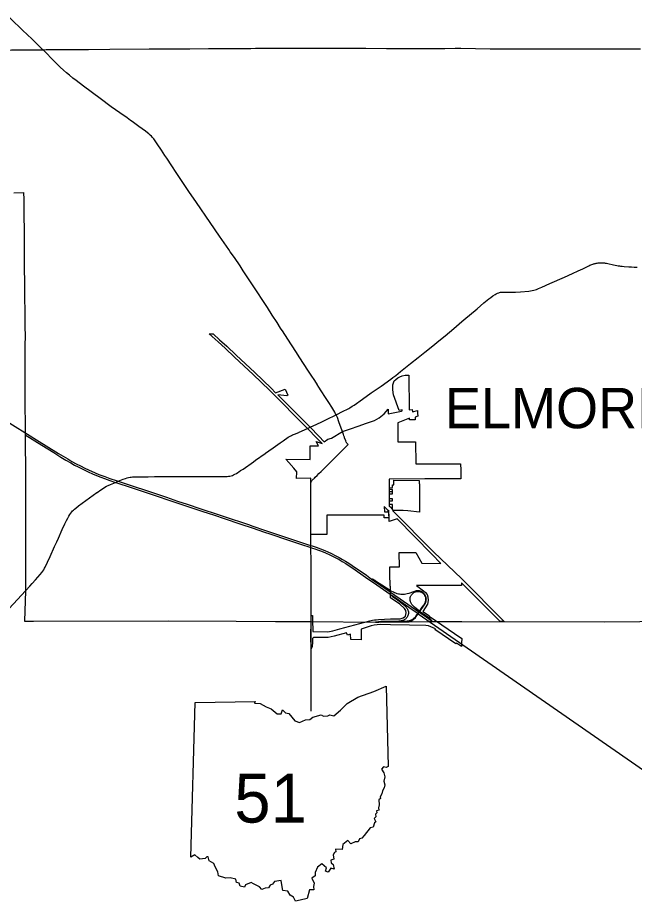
# Model space of a CAD drawing. Extents: x -82 to 873, y 0 to 440.
# Drawn here: x 144.2 to 201.4, y 99.3 to 181.3 of the extents above; entities that cross this region are included whole.
import ezdxf

# ---------------------------------------------------------------- set-up
doc = ezdxf.new("R2010")
doc.units = 0
for name, color, linetype in [('DV_X_Corp_Line', 7, 'Continuous'), ('GM_X_Corporation_Text', 7, 'Continuous'), ('GM_X_County', 7, 'Continuous'), ('GM_X_Interchange_Ramps', 7, 'Continuous'), ('GM_X_Interstate_Route', 7, 'Continuous'), ('PV_P_Text', 7, 'Continuous')]:
    doc.layers.add(name, color=color, linetype=linetype)

msp = doc.modelspace()

# ---------------------------------------------------------------- linework, layer by layer
at = {"layer": 'DV_X_Corp_Line'}
for points in [[(179.016, 136.129), (178.715, 136.13), (178.711, 136.47), (179.014, 136.47), (179.014, 136.675), (178.714, 136.673), (178.714, 137.127), (179.014, 137.127), (179.014, 137.3), (178.716, 137.303), (178.716, 137.341), (179.013, 137.336), (179.008, 137.524), (178.715, 137.518), (178.717, 137.692), (179.014, 137.701), (179.014, 137.971), (179.121, 137.969), (179.121, 138.394), (181.477, 138.368), (181.484, 138.061), (181.499, 138.061), (181.5, 135.421), (180.425, 135.553), (180, 135.568), (179, 135.585), (182.828, 131.714), (185.396, 129.272), (189.374, 125.272), (189.003, 125.269), (185.4, 128.867), (185.402, 128.61), (181.24, 128.609), (181.868, 128.129), (182.061, 127.98), (182.212, 127.777), (182.287, 127.55), (182.313, 127.229), (182.239, 126.882), (181.822, 126.214), (182.425, 125.789), (182.418, 125.779), (184.746, 124.15), (185.423, 123.712), (185.418, 123.308), (185.418, 122.954), (184.928, 123.275), (184.893, 123.195), (182.927, 124.523), (182.979, 124.593), (182.34, 124.875), (182.091, 124.912), (180.589, 124.944), (178.818, 124.972), (177.857, 124.998), (177.579, 124.975), (177.295, 124.931), (177.037, 124.866), (176.088, 124.577), (176.1, 123.575), (175.13, 123.592), (175.119, 124.111), (174.835, 124.015), (174.729, 124.217), (173.589, 123.905), (173.027, 123.794), (171.669, 123.789), (171.588, 123.69), (171.584, 123.581), (171.582, 123.347), (171.558, 122.96), (171.439, 122.724), (171.436, 123.903), (171.457, 125.272), (171.454, 125.599), (171.454, 125.836), (171.569, 125.836), (171.575, 125.423), (171.617, 124.334), (172.997, 124.31), (173.463, 124.397), (174.112, 124.595), (176.891, 125.324), (177.139, 125.389), (177.33, 125.432), (177.494, 125.445), (177.712, 125.463), (178.813, 125.508), (179.704, 125.518), (180.003, 125.606), (180.195, 125.758), (180.281, 126.064), (180.226, 126.288), (180.108, 126.472), (179.68, 126.888), (178.829, 127.485), (178.826, 127.79), (178.825, 128), (178.815, 128.567), (178.775, 128.566), (178.774, 128.893), (178.768, 129.372), (178.766, 129.756), (178.76, 130.34), (179.652, 130.335), (179.612, 131.672), (181.159, 131.675), (181.739, 130.694), (183.503, 130.668), (182.651, 131.538), (179.433, 134.791), (178.681, 134.57), (178.666, 135.576), (178.632, 135.6), (178.65, 134.888), (178.214, 134.889), (178.219, 135.16), (172.91, 135.139), (172.92, 133.338), (171.428, 133.348), (171.427, 133.873), (171.425, 134.467), (171.424, 134.929), (171.423, 135.591), (171.422, 135.727), (171.423, 136.756), (171.423, 137.167), (171.414, 137.659), (171.411, 137.825), (171.413, 137.985), (171.416, 138.046), (171.414, 138.574), (170.079, 138.564), (170.11, 139.154), (169.837, 139.512), (169.37, 140.04), (169.101, 140.347), (171.357, 140.315), (171.374, 141.578), (172.134, 141.569), (171.922, 141.971), (172.47, 141.797), (171.983, 142.306), (171.124, 143.192), (167.572, 146.745), (166.084, 148.195), (164.34, 149.801), (163.464, 150.646), (162.813, 151.236), (161.979, 151.978), (162.296, 151.984), (162.365, 151.986), (162.956, 151.416), (163.62, 150.822), (164.501, 149.984), (166.234, 148.388), (167.743, 146.92), (168.155, 146.508), (169.039, 146.847), (169.279, 146.295), (169.195, 146.219), (168.353, 146.31), (171.365, 143.3), (172.172, 142.467), (172.648, 141.96), (172.998, 142.196), (173.339, 142.304), (174.353, 142.897), (174.719, 143.046), (175.094, 143.17), (175.808, 143.405), (176.603, 143.688), (177.335, 143.927), (177.761, 144.175), (178.232, 144.563), (178.596, 144.992), (178.589, 144.537), (179.847, 144.81), (179.915, 144.825), (179.886, 144.932), (179.634, 144.865), (179.109, 146.318), (179.047, 146.769), (179.024, 147.245), (179.087, 147.428), (179.169, 147.615), (179.297, 147.749), (179.491, 147.893), (179.681, 147.999), (179.892, 148.077), (180.187, 148.149), (180.504, 148.155), (180.558, 144.922), (180.83, 144.964), (180.846, 144.734), (181.315, 144.846), (181.319, 144.797), (181.332, 144.62), (181.349, 144.324), (181.111, 144.247), (181.113, 144.006), (180.59, 143.987), (180.585, 144.142), (179.497, 143.712), (179.507, 141.967), (181.141, 141.961), (181.16, 139.899), (185.328, 139.899), (185.335, 139.333), (185.338, 139.02), (185.336, 138.723), (185.33, 138.513), (185.232, 138.515), (184.46, 138.513), (183.965, 138.511), (183.93, 138.511), (183.515, 138.51), (182.824, 138.511), (182.528, 138.51), (182.208, 138.508), (181.999, 138.506), (178.682, 138.484), (178.681, 138.206), (178.683, 137.845), (178.685, 137.707), (178.687, 137.534), (178.688, 137.4), (178.689, 137.358), (178.69, 137.142), (178.691, 136.917), (178.692, 136.69), (178.692, 136.542), (178.693, 136.338), (178.692, 135.979), (178.737, 135.935), (178.778, 135.904), (179.004, 135.682)], [(178.255, 135.463), (178.614, 135.469), (178.611, 135.593), (178.241, 135.959)]]:
    msp.add_lwpolyline(points, close=True, dxfattribs=at)
at = {"layer": 'GM_X_County'}
msp.add_lwpolyline([(143.85, 165.07), (144.77, 165.089), (144.77, 165.041), (144.78, 164.504), (144.789, 163.971), (144.79, 163.519), (144.796, 163.15), (144.798, 162.74), (144.811, 161.795), (144.814, 161.344), (144.824, 160.604), (144.827, 159.823), (144.829, 159.251), (144.833, 157.978), (144.845, 156.829), (144.861, 155.064), (144.866, 154.325), (144.878, 153.422), (144.894, 152.599), (144.896, 151.825), (144.883, 150.878), (144.878, 149.313), (144.881, 148.294), (144.89, 145.706), (144.895, 144.846), (144.896, 144.066), (144.904, 143.224), (144.905, 143.012), (144.907, 142.801), (144.907, 142.592), (144.912, 142.094), (144.913, 141.559), (144.916, 141.23), (144.929, 139.958), (144.931, 139.674), (144.935, 139.26), (144.939, 138.645), (144.941, 138.357), (144.937, 137.742), (144.937, 137.249), (144.935, 136.51), (144.936, 135.032), (144.94, 133.883), (144.942, 132.323), (144.95, 129.655), (144.947, 128.546), (144.95, 128.402), (144.955, 128.137), (144.843, 125.317), (145.683, 125.315), (158.213, 125.324), (164.501, 125.302), (168.138, 125.28), (171.457, 125.272), (177.433, 125.221), (177.739, 125.221), (178.815, 125.23), (180.54, 125.248), (182.454, 125.267), (182.74, 125.268), (185.433, 125.276), (198.647, 125.256), (205.258, 125.298)], dxfattribs=at)
at = {"layer": 'GM_X_Interchange_Ramps'}
for points in [[(180.54, 125.248), (180.607, 125.267), (180.666, 125.285), (180.727, 125.307), (180.804, 125.345), (180.87, 125.387), (180.931, 125.426), (180.994, 125.482), (181.056, 125.541), (181.126, 125.629), (181.202, 125.726), (181.397, 126.001), (181.493, 126.137), (181.541, 126.205), (181.882, 126.699), (181.995, 126.869), (182.056, 126.976), (182.089, 127.051), (182.103, 127.089), (182.125, 127.168), (182.139, 127.248), (182.144, 127.33), (182.14, 127.411), (182.128, 127.492), (182.108, 127.572), (182.079, 127.648), (182.043, 127.722), (182, 127.791), (181.949, 127.856), (181.892, 127.914), (181.83, 127.967), (181.763, 128.014), (181.691, 128.053), (181.615, 128.084), (181.576, 128.097), (181.496, 128.116), (181.456, 128.122), (181.375, 128.127), (181.334, 128.127), (181.252, 128.12), (181.212, 128.114), (181.093, 128.084), (180.937, 128.033), (180.512, 127.884), (180.355, 127.836), (180.236, 127.808), (180.114, 127.79), (180.033, 127.783), (179.91, 127.781), (179.788, 127.788), (179.666, 127.802), (179.545, 127.824), (179.425, 127.853), (179.308, 127.89), (179.194, 127.934), (179.082, 127.985), (178.937, 128.06), (178.825, 128.126), (178.784, 128.151), (178.449, 128.362), (178.252, 128.49), (177.524, 128.967), (177.367, 129.072), (177.292, 129.118), (177.218, 129.161), (177.197, 129.172), (177.179, 129.181), (177.141, 129.195), (177.125, 129.202), (177.099, 129.21), (177.062, 129.219)], [(182.669, 125.316), (182.624, 125.381), (182.606, 125.406), (182.579, 125.437), (182.552, 125.468), (182.498, 125.52), (182.401, 125.601), (182.367, 125.624), (181.983, 125.887), (181.613, 126.151), (181.541, 126.205), (181.385, 126.326), (181.196, 126.482), (181.042, 126.618), (180.951, 126.701), (180.865, 126.789), (180.812, 126.851), (180.763, 126.917), (180.721, 126.988), (180.702, 127.024), (180.671, 127.1), (180.658, 127.138), (180.639, 127.218), (180.631, 127.299), (180.631, 127.381), (180.641, 127.462), (180.649, 127.503), (180.672, 127.581), (180.703, 127.657), (180.722, 127.694), (180.765, 127.764), (180.817, 127.827), (180.845, 127.857), (180.907, 127.91), (180.94, 127.934), (180.975, 127.956), (181.048, 127.993), (181.124, 128.023), (181.204, 128.045), (181.284, 128.058), (181.366, 128.063), (181.448, 128.058), (181.489, 128.052), (181.569, 128.034), (181.608, 128.021), (181.683, 127.989), (181.719, 127.97), (181.788, 127.925), (181.82, 127.9), (181.88, 127.844), (181.933, 127.782), (181.979, 127.714), (182.017, 127.641), (182.034, 127.603), (182.059, 127.525), (182.068, 127.486), (182.08, 127.405), (182.082, 127.364), (182.079, 127.282), (182.068, 127.201), (182.048, 127.122), (182.035, 127.083), (182.004, 127.008), (181.967, 126.935), (181.903, 126.829), (181.739, 126.594), (181.443, 126.173), (181.346, 126.038), (181.337, 126.025), (181.171, 125.79), (181.097, 125.692), (181.044, 125.63), (180.987, 125.571), (180.926, 125.516), (180.862, 125.466), (180.793, 125.422), (180.72, 125.385), (180.644, 125.354), (180.564, 125.329), (180.486, 125.312), (180.365, 125.295), (180.241, 125.289), (179.97, 125.288), (179.581, 125.294), (178.817, 125.277), (178.715, 125.277), (177.921, 125.272), (177.699, 125.257), (177.433, 125.221)], [(178.826, 127.79), (178.894, 127.712), (178.951, 127.651), (179.017, 127.599), (179.09, 127.545), (179.48, 127.273), (179.677, 127.126), (179.869, 126.973), (180.055, 126.812), (180.175, 126.7), (180.26, 126.612), (180.312, 126.549), (180.359, 126.482), (180.4, 126.411), (180.434, 126.336), (180.461, 126.259), (180.478, 126.179), (180.486, 126.098), (180.486, 126.057), (180.483, 126.016), (180.471, 125.936), (180.461, 125.896), (180.435, 125.818), (180.401, 125.743), (180.36, 125.672), (180.312, 125.606), (180.256, 125.546), (180.226, 125.518), (180.194, 125.493), (180.126, 125.447), (180.065, 125.411), (179.978, 125.371), (179.934, 125.355), (179.883, 125.34), (179.847, 125.332), (179.818, 125.325), (179.747, 125.313), (179.695, 125.305), (179.581, 125.294)]]:
    msp.add_lwpolyline(points, dxfattribs=at)
at = {"layer": 'GM_X_Interstate_Route'}
msp.add_line((109.105, 164.804), (145.117, 142.669), dxfattribs=at)
for points in [[(146.548, 178.353), (146.523, 178.377), (146.166, 178.724), (145.614, 179.254), (145.028, 179.812), (144.75, 180.079), (144.343, 180.47), (143.892, 180.895), (143.546, 181.233), (143.505, 181.272), (143.449, 181.324)], [(141.437, 178.319), (143.641, 178.332), (144.298, 178.338), (144.728, 178.343), (145.621, 178.347), (146.548, 178.353)], [(146.548, 178.353), (146.852, 178.355), (148.165, 178.362), (149.027, 178.371), (150.791, 178.379), (152.761, 178.394), (156.413, 178.419), (157.726, 178.432), (158.017, 178.434), (160.189, 178.446), (161.912, 178.454), (162.856, 178.46), (163.964, 178.464), (164.422, 178.467)], [(171.58, 147.954), (171.335, 148.329), (171.152, 148.62), (170.413, 149.756), (170.032, 150.341), (169.294, 151.477), (169.066, 151.818), (168.939, 152.019), (168.847, 152.164), (168.623, 152.509), (168.291, 153.027), (167.845, 153.716), (167.399, 154.406), (167.156, 154.786), (166.91, 155.165), (166.511, 155.787), (165.833, 156.815), (165.149, 157.839), (164.856, 158.285), (164.325, 159.066), (163.948, 159.604), (163.814, 159.798), (163.389, 160.415), (162.943, 161.055), (162.081, 162.305), (160.809, 164.17), (160.115, 165.197), (158.932, 166.964), (158.523, 167.579), (158.059, 168.278), (157.886, 168.536), (157.564, 169.012), (157.154, 169.627), (156.968, 169.898), (156.846, 170.064), (156.743, 170.192), (156.632, 170.314), (156.515, 170.43), (156.392, 170.54), (156.265, 170.644), (156.068, 170.793), (155.469, 171.226), (154.832, 171.676), (154.689, 171.779), (154.366, 172.013), (153.696, 172.486), (152.897, 173.063), (151.87, 173.814), (150.323, 174.967), (149.634, 175.485), (149.344, 175.713), (149.026, 175.973), (148.746, 176.213), (148.471, 176.459), (148.171, 176.739), (147.614, 177.284), (146.647, 178.262), (146.548, 178.353)], [(164.422, 178.467), (165.277, 178.473), (165.852, 178.474), (166.303, 178.48), (168.396, 178.488), (168.888, 178.495), (169.956, 178.496), (171.314, 178.496), (171.556, 178.496), (172.048, 178.498), (172.91, 178.491), (173.533, 178.492), (173.895, 178.493), (175.742, 178.49), (176.398, 178.484), (176.519, 178.484), (178.45, 178.477), (179.763, 178.468), (181.035, 178.461), (181.651, 178.458), (182.677, 178.462), (183.867, 178.473), (184.81, 178.486), (185.237, 178.488), (185.344, 178.488), (188.052, 178.446), (190.063, 178.433), (190.966, 178.43), (191.664, 178.431), (192.443, 178.429), (193.141, 178.429), (194.823, 178.429), (196.465, 178.432), (197.286, 178.432), (198.353, 178.436), (198.445, 178.436), (198.968, 178.437), (199.625, 178.441), (200.446, 178.437), (202.005, 178.428)], [(173.774, 144.472), (174.421, 144.785), (174.836, 144.991), (174.946, 145.05), (175.049, 145.111), (175.268, 145.248), (175.45, 145.371), (176.231, 145.921), (177.036, 146.493), (177.942, 147.129), (178.835, 147.764), (179.046, 147.914), (179.308, 148.111), (179.759, 148.466), (180.683, 149.216), (181.386, 149.782), (181.993, 150.272), (182.731, 150.861), (183.306, 151.324), (183.878, 151.791), (184.291, 152.128), (184.7, 152.471), (185.44, 153.107), (185.634, 153.273), (186.854, 154.309), (187.167, 154.574), (187.479, 154.84), (187.794, 155.103), (187.955, 155.23), (188.121, 155.352), (188.324, 155.491), (188.532, 155.624), (188.639, 155.686), (188.75, 155.741), (188.865, 155.788), (188.944, 155.814), (189.024, 155.834), (189.106, 155.848), (189.188, 155.856), (189.312, 155.86), (189.64, 155.853), (189.845, 155.847), (190.132, 155.85), (190.419, 155.86), (190.868, 155.891), (191.646, 155.952), (191.808, 155.971), (191.969, 155.998), (192.129, 156.034), (192.247, 156.067), (192.363, 156.106), (192.553, 156.18), (192.854, 156.312), (193.603, 156.646), (194.957, 157.242), (195.703, 157.574), (196.228, 157.811), (196.67, 158.023), (197.222, 158.293), (197.308, 158.338), (197.408, 158.382), (197.502, 158.42), (197.582, 158.449), (197.658, 158.473), (197.719, 158.49), (197.786, 158.507), (197.849, 158.52), (197.913, 158.531), (197.993, 158.544), (198.075, 158.553), (198.165, 158.561), (198.291, 158.568), (198.414, 158.57), (198.536, 158.566), (198.567, 158.564), (198.664, 158.557), (198.742, 158.548), (198.803, 158.539), (198.86, 158.528), (198.988, 158.5), (199.507, 158.381), (199.676, 158.343), (199.826, 158.313), (199.933, 158.293), (200.055, 158.274), (200.167, 158.261), (200.328, 158.245), (200.508, 158.232), (200.926, 158.2), (201.173, 158.186), (201.438, 158.169), (201.723, 158.156)], [(173.774, 144.472), (173.724, 144.565), (173.646, 144.709), (173.559, 144.849), (173.363, 145.162), (173.08, 145.615), (172.794, 146.065), (172.391, 146.685), (172.171, 147.031), (172.015, 147.273), (171.998, 147.3), (171.663, 147.827), (171.58, 147.954)], [(171.37, 143.303), (171.994, 143.588), (172.442, 143.797), (172.808, 143.983), (173.139, 144.151), (173.193, 144.177), (173.472, 144.313), (173.774, 144.472)], [(174.447, 142.634), (174.353, 142.897), (174.288, 143.079), (174.06, 143.718), (174.023, 143.82), (173.884, 144.206), (173.837, 144.322), (173.81, 144.387), (173.774, 144.472)], [(144.907, 142.801), (145.117, 142.669), (145.96, 142.147), (148.018, 140.872), (148.86, 140.361), (149.25, 140.135), (149.646, 139.918), (150.046, 139.709), (150.45, 139.508), (150.784, 139.351), (151.421, 139.069), (151.763, 138.929), (152.299, 138.724), (152.762, 138.556), (153.344, 138.359), (153.547, 138.292), (154.277, 138.05), (156.809, 137.212), (158.015, 136.808), (159.064, 136.452), (159.96, 136.157), (161.206, 135.744), (162.725, 135.241), (163.385, 135.016), (165.644, 134.265), (166.052, 134.126), (167.127, 133.76), (171.205, 132.399), (171.427, 132.325), (171.557, 132.287), (171.906, 132.166), (172.329, 132.01), (172.71, 131.858), (173.012, 131.728), (173.347, 131.573), (173.679, 131.411), (174.043, 131.221), (174.365, 131.041), (174.648, 130.874), (174.96, 130.678), (175.268, 130.474), (176.583, 129.562), (177.062, 129.219), (177.875, 128.66), (178.781, 128.031), (178.825, 128), (179.704, 127.389), (181.443, 126.173), (181.493, 126.137), (182.115, 125.704), (182.669, 125.316), (182.74, 125.268)], [(155.311, 138.705), (155.42, 138.708), (156.32, 138.713), (156.901, 138.72), (157.757, 138.725), (158.162, 138.726), (158.455, 138.727), (158.868, 138.728), (159.235, 138.73), (160.427, 138.732), (161.781, 138.738), (162.232, 138.738), (162.972, 138.742), (163.489, 138.744), (163.667, 138.749), (163.792, 138.758), (163.913, 138.777), (164.031, 138.804), (164.147, 138.842), (164.26, 138.89), (164.37, 138.944), (164.512, 139.024), (164.86, 139.245), (164.909, 139.277), (165.135, 139.423), (166.112, 140.107), (166.302, 140.244), (167.178, 140.871), (167.214, 140.897), (167.512, 141.107), (167.917, 141.396), (168.583, 141.868), (168.854, 142.054), (169.333, 142.372), (169.508, 142.48), (169.616, 142.541), (169.726, 142.595), (169.915, 142.677), (170.297, 142.828), (170.343, 142.848)], [(170.343, 142.848), (171.124, 143.192), (171.129, 143.194)], [(171.129, 143.194), (171.365, 143.3), (171.37, 143.303)], [(144.907, 142.592), (146.452, 141.639), (147.569, 140.949), (148.229, 140.535), (148.686, 140.261), (149.146, 139.993), (149.504, 139.794), (149.831, 139.623), (150.271, 139.403), (150.752, 139.174), (151.163, 138.99), (151.539, 138.829), (151.919, 138.676), (152.264, 138.546), (152.767, 138.371), (153.3, 138.191), (153.335, 138.18)], [(174.492, 142.51), (174.447, 142.634)], [(174.891, 141.703), (174.863, 141.722), (174.838, 141.74), (174.811, 141.766), (174.784, 141.798), (174.76, 141.834), (174.734, 141.877), (174.708, 141.933), (174.664, 142.04), (174.563, 142.315), (174.542, 142.373), (174.492, 142.51)], [(174.032, 140.845), (174.367, 141.178), (174.891, 141.703)], [(171.421, 138.093), (171.421, 138.097), (171.432, 138.151), (171.446, 138.199), (171.465, 138.244), (171.494, 138.304), (171.523, 138.343), (171.562, 138.39), (171.617, 138.45), (171.645, 138.477), (171.692, 138.524), (171.754, 138.587), (171.831, 138.661), (172.008, 138.837), (172.18, 139.004), (172.382, 139.209), (172.585, 139.412), (172.626, 139.451), (172.826, 139.642), (172.992, 139.809), (173.52, 140.336), (173.64, 140.454), (174.032, 140.845)], [(151.559, 137.237), (151.593, 137.262), (151.929, 137.499), (152.168, 137.659), (152.308, 137.746), (152.452, 137.826), (152.599, 137.899), (152.825, 137.998), (153.3, 138.191), (153.547, 138.292), (154.005, 138.479), (154.214, 138.555), (154.363, 138.601), (154.51, 138.64), (154.641, 138.665), (154.76, 138.681), (154.885, 138.691), (155.047, 138.699), (155.311, 138.705)], [(153.335, 138.18), (154.75, 137.704), (157.163, 136.901), (158.252, 136.538), (160.198, 135.889), (161.403, 135.485), (162.377, 135.163), (163.466, 134.799), (164.829, 134.347), (166.077, 133.93), (167.034, 133.61), (167.706, 133.382), (169.261, 132.861), (170.468, 132.461), (171.426, 132.142), (171.571, 132.094)], [(171.426, 133.997), (171.425, 134.467), (171.424, 134.929), (171.423, 135.591), (171.422, 135.727), (171.423, 136.756), (171.423, 137.167), (171.414, 137.659), (171.411, 137.825), (171.413, 137.985), (171.416, 138.046), (171.421, 138.093)], [(139.193, 121.929), (145.336, 128.548), (145.557, 128.791), (145.857, 129.129), (146.318, 129.653), (146.448, 129.811), (146.545, 129.942), (146.634, 130.079), (146.719, 130.22), (146.777, 130.327), (146.989, 130.772), (147.228, 131.295), (147.648, 132.231), (147.85, 132.681), (148.002, 133.017), (148.351, 133.806), (148.591, 134.328), (148.75, 134.662), (148.864, 134.881), (148.966, 135.06), (149.052, 135.2), (149.145, 135.336), (149.246, 135.467), (149.309, 135.539), (149.384, 135.617), (149.478, 135.701), (149.606, 135.805), (149.87, 136.002), (150.216, 136.255), (151.559, 137.237)], [(171.428, 133.336), (171.428, 133.348), (171.427, 133.873), (171.426, 133.997)], [(171.429, 132.014), (171.426, 132.142), (171.427, 132.325), (171.432, 132.859), (171.428, 133.336)], [(171.571, 132.094), (171.791, 132.022), (172.14, 131.898), (172.408, 131.794), (172.787, 131.635), (173.199, 131.451), (173.496, 131.31), (173.753, 131.18), (174.041, 131.022), (174.326, 130.858), (174.678, 130.645), (174.989, 130.447), (175.33, 130.218), (176.508, 129.396), (177.552, 128.671), (178.157, 128.247), (178.783, 127.819), (178.826, 127.79), (179.037, 127.644)], [(171.455, 116.945), (171.454, 125.836), (171.454, 125.927), (171.455, 125.987), (171.457, 126.378), (171.455, 127.527), (171.453, 128.06), (171.449, 128.593), (171.446, 129.537), (171.444, 130.234), (171.44, 131.136), (171.436, 131.792), (171.429, 132.014)], [(179.037, 127.644), (179.774, 127.133), (180.746, 126.456)], [(180.746, 126.456), (181.346, 126.038), (181.397, 126.001), (210.684, 105.646)], [(171.457, 125.272), (171.454, 125.599), (171.454, 125.801)]]:
    msp.add_lwpolyline(points, dxfattribs=at)
at = {"layer": 'PV_P_Text'}
msp.add_line((160.293, 103.406), (160.694, 117.769), dxfattribs=at)
msp.add_line((160.293, 103.406), (160.694, 117.769), dxfattribs=at)
for points in [[(160.694, 117.769), (166.267, 117.863), (166.18, 117.689), (166.706, 117.653), (167.264, 117.346), (167.736, 117.153), (168.314, 116.696), (168.66, 116.701), (168.806, 117.075), (169.071, 116.786), (169.385, 116.735), (169.929, 116.047), (170.377, 115.899), (170.914, 116.134), (171.316, 116.173), (171.609, 116.406), (172.374, 116.605), (172.587, 116.486), (172.992, 116.51), (173.196, 116.598), (173.549, 116.519), (174.17, 117.042), (174.81, 117.658), (175.794, 118.239), (177.264, 118.789), (178.427, 119.282), (178.595, 111.828)], [(160.694, 117.769), (166.267, 117.863), (166.18, 117.689), (166.706, 117.653), (167.264, 117.346), (167.736, 117.153), (168.314, 116.696), (168.66, 116.701), (168.806, 117.075), (169.071, 116.786), (169.385, 116.735), (169.929, 116.047), (170.377, 115.899), (170.914, 116.134), (171.316, 116.173), (171.609, 116.406), (172.374, 116.605), (172.587, 116.486), (172.992, 116.51), (173.196, 116.598), (173.549, 116.519), (174.17, 117.042), (174.81, 117.658), (175.794, 118.239), (177.264, 118.789), (178.427, 119.282), (178.595, 111.828)], [(178.595, 111.828), (178.424, 111.724), (178.157, 111.773), (177.977, 111.564), (178.199, 111.215), (178.304, 110.847), (178.211, 110.44), (178.303, 110.105), (178.241, 109.825), (178.073, 109.546), (178.015, 109.28), (177.872, 109), (177.884, 108.843), (177.748, 108.719), (177.773, 108.252), (177.704, 107.994), (177.728, 107.771), (177.507, 107.713), (177.558, 107.529), (177.417, 107.386), (177.447, 107.142), (177.288, 106.986), (177.443, 106.673), (177.319, 106.574), (177.216, 106.193), (176.933, 106.116), (176.366, 105.421), (176.166, 105.158), (175.941, 105.092), (175.818, 104.822), (175.541, 104.821), (175.123, 104.634), (174.852, 104.956), (174.378, 104.568), (174.323, 104.12), (173.724, 104.135), (173.747, 103.908), (173.613, 103.842), (173.491, 103.615), (173.562, 103.212), (173.282, 103.11), (173.316, 102.875), (173.495, 102.732), (173.575, 102.285), (173.277, 102.376), (173.033, 101.999), (172.782, 102.087), (172.864, 102.407), (172.439, 102.79), (172.037, 102.483), (171.828, 101.991), (171.826, 101.661), (171.526, 101.461), (171.718, 100.994), (171.683, 100.672), (171.689, 100.367), (171.315, 100.377), (171.089, 99.553)], [(178.595, 111.828), (178.424, 111.724), (178.157, 111.773), (177.977, 111.564), (178.199, 111.215), (178.304, 110.847), (178.211, 110.44), (178.303, 110.105), (178.241, 109.825), (178.073, 109.546), (178.015, 109.28), (177.872, 109), (177.884, 108.843), (177.748, 108.719), (177.773, 108.252), (177.704, 107.994), (177.728, 107.771), (177.507, 107.713), (177.558, 107.529), (177.417, 107.386), (177.447, 107.142), (177.288, 106.986), (177.443, 106.673), (177.319, 106.574), (177.216, 106.193), (176.933, 106.116), (176.366, 105.421), (176.166, 105.158), (175.941, 105.092), (175.818, 104.822), (175.541, 104.821), (175.123, 104.634), (174.852, 104.956), (174.378, 104.568), (174.323, 104.12), (173.724, 104.135), (173.747, 103.908), (173.613, 103.842), (173.491, 103.615), (173.562, 103.212), (173.282, 103.11), (173.316, 102.875), (173.495, 102.732), (173.575, 102.285), (173.277, 102.376), (173.033, 101.999), (172.782, 102.087), (172.864, 102.407), (172.439, 102.79), (172.037, 102.483), (171.828, 101.991), (171.826, 101.661), (171.526, 101.461), (171.718, 100.994), (171.683, 100.672), (171.689, 100.367), (171.315, 100.377), (171.089, 99.553)], [(171.089, 99.553), (170.438, 99.395), (169.987, 99.301), (169.828, 99.675), (169.505, 99.873), (169.295, 100.25), (168.831, 100.301), (168.721, 100.819), (168.669, 101.239), (168.036, 101.135), (167.862, 100.879), (167.637, 100.809), (167.506, 100.551), (167.2, 100.529), (166.871, 100.407), (166.656, 100.661), (166.117, 100.916), (165.875, 101.047), (165.369, 100.843), (165.261, 100.601), (164.857, 100.707), (164.763, 100.977), (164.519, 101.058), (164.465, 101.344), (163.944, 101.496), (163.545, 101.436), (162.841, 101.666), (162.798, 102.042), (162.559, 102.501), (162.434, 102.82), (161.989, 103.063), (161.899, 103.441), (161.757, 103.43), (161.627, 103.276), (161.133, 103.206), (160.935, 103.361), (160.659, 103.625), (160.293, 103.406)], [(171.089, 99.553), (170.438, 99.395), (169.987, 99.301), (169.828, 99.675), (169.505, 99.873), (169.295, 100.25), (168.831, 100.301), (168.721, 100.819), (168.669, 101.239), (168.036, 101.135), (167.862, 100.879), (167.637, 100.809), (167.506, 100.551), (167.2, 100.529), (166.871, 100.407), (166.656, 100.661), (166.117, 100.916), (165.875, 101.047), (165.369, 100.843), (165.261, 100.601), (164.857, 100.707), (164.763, 100.977), (164.519, 101.058), (164.465, 101.344), (163.944, 101.496), (163.545, 101.436), (162.841, 101.666), (162.798, 102.042), (162.559, 102.501), (162.434, 102.82), (161.989, 103.063), (161.899, 103.441), (161.757, 103.43), (161.627, 103.276), (161.133, 103.206), (160.935, 103.361), (160.659, 103.625), (160.293, 103.406)]]:
    msp.add_lwpolyline(points, dxfattribs=at)

# ---------------------------------------------------------------- texts
at = {"layer": 'GM_X_Corporation_Text'}
msp.add_text('ELMORE', height=3.75, rotation=0.00501, dxfattribs=at).set_placement((183.873, 143.21))
at = {"layer": 'PV_P_Text'}
msp.add_text('51', height=4.5281, rotation=0.005, dxfattribs=at).set_placement((164.32, 106.609))

doc.saveas('drawing.dxf')
